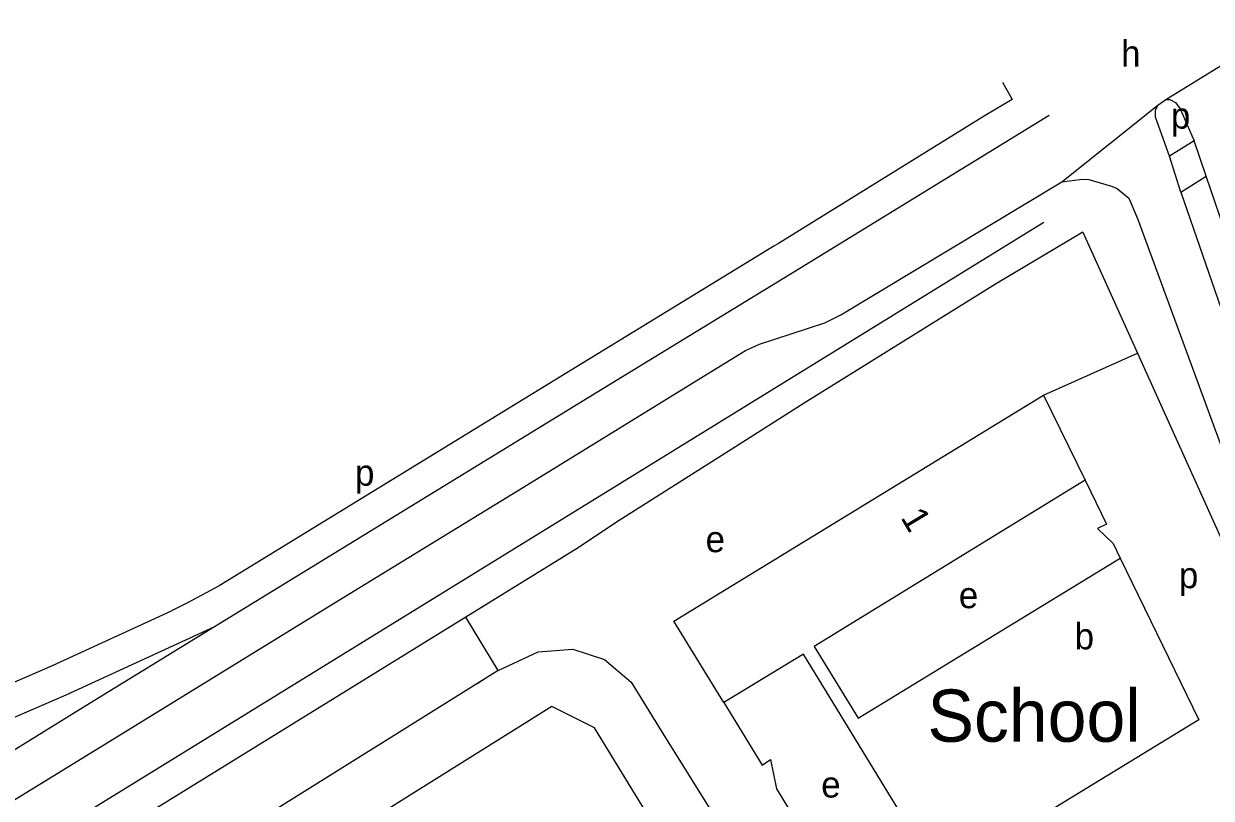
# Model space of a CAD drawing. Extents: x 158848 to 160613, y 385889 to 387762.
# Drawn here: x 158951 to 159133.1, y 387265.7 to 387384.4 of the extents above; entities that cross this region are included whole.
import ezdxf

# ---------------------------------------------------------------- set-up
doc = ezdxf.new("R2010")
doc.units = 0
for name, color, linetype in [('BLT_Basislijn', 7, 'Continuous'), ('BLT_Bebouwing', 7, 'Continuous'), ('BLT_Bebouwing_beschrifting', 7, 'Continuous'), ('BLT_Centroide', 7, 'Continuous'), ('BLT_Huisnummer', 7, 'Continuous'), ('BLT_Vlakafsluiter', 7, 'Continuous')]:
    doc.layers.add(name, color=color, linetype=linetype)

msp = doc.modelspace()

# ---------------------------------------------------------------- linework, layer by layer
at = {"layer": 'BLT_Basislijn'}
for p, q in [((159101.06, 387375.39), (159102.57, 387372.74)), ((159124.9, 387371.86), (159126.12, 387372.74)), ((159108.24, 387370.28), (159069.34, 387346.44)), ((159130.47, 387366.4), (159126.7, 387364.08)), ((159132.32, 387361.01), (159130.47, 387366.4)), ((159128.43, 387358.56), (159126.7, 387364.08)), ((159128.43, 387358.56), (159132.32, 387361.01)), ((159065.99, 387350.25), (159036.54, 387332.25)), ((159069.34, 387346.44), (159039.15, 387327.99)), ((159107.38, 387327.45), (159121.8, 387333.85)), ((159039.15, 387327.99), (158980.27, 387291.91)), ((159070.65, 387326.21), (159059.57, 387319.18)), ((159036.03, 387304.04), (159018.8, 387293.41)), ((158976.2, 387295.64), (158973.67, 387294.39)), ((159018.8, 387293.41), (158948.38, 387250)), ((159023.73, 387285.24), (159018.8, 387293.41)), ((158980.27, 387291.91), (158961.17, 387280.21)), ((159023.73, 387285.24), (158967.29, 387250)), ((158961.17, 387280.21), (158899.9, 387242.56)), ((159048.76, 387276.01), (159064.96, 387250))]:
    msp.add_line(p, q, dxfattribs=at)
for points in [[(159102.57, 387372.74), (159098.41, 387370.27), (159066.73, 387350.7), (159065.99, 387350.25)], [(159126.12, 387372.74), (159126.75, 387372.74), (159127.6, 387372.26), (159128.31, 387371.3), (159130.47, 387366.4)], [(159126.7, 387364.08), (159124.55, 387370.05), (159124.55, 387371.12), (159124.9, 387371.86)], [(158888.87, 387228.17), (158897.56, 387233.51), (158936.43, 387257.38), (158966.21, 387275.66), (158998.48, 387295.52), (159028.3, 387313.75), (159057.18, 387331.51), (159061.69, 387334.26), (159063.8, 387335.23), (159073.81, 387338.52), (159076.27, 387339.74), (159110.17, 387360.14)], [(159110.17, 387360.14), (159113.36, 387360.52), (159114.33, 387360.5), (159117.81, 387359.48), (159118.66, 387359.09), (159120.45, 387357.64), (159121.8, 387354.51)], [(159128.43, 387358.56), (159135.58, 387337.85), (159148.17, 387304.4), (159154.58, 387289.64), (159157.42, 387290.35), (159158.28, 387290.99), (159158.28, 387291.47), (159151.86, 387306.88), (159139.89, 387338.89), (159132.32, 387361.01)], [(159121.8, 387354.51), (159136.23, 387315.16), (159143.84, 387296.72), (159149.58, 387283.82)], [(158866.04, 387201.65), (158878.3, 387211.25), (158882.68, 387215.41), (158895.2, 387223.16), (158941.52, 387251.8), (159042.66, 387314.04), (159107.41, 387353.95)], [(159113.41, 387352.43), (159100, 387344.45), (159070.65, 387326.21)], [(159113.41, 387352.43), (159121.8, 387333.85)], [(159121.8, 387333.85), (159149.98, 387271.42)], [(159036.54, 387332.25), (158980.95, 387298.19), (158976.2, 387295.64)], [(159059.57, 387319.18), (159041.76, 387307.88), (159036.03, 387304.04)], [(159113.74, 387314.39), (159117, 387307.66), (159115.62, 387307.02), (159118.04, 387304.68), (159119.13, 387302.43)], [(158942.51, 387280.45), (158955.4, 387286.01), (158973.67, 387294.39)], [(158980.27, 387291.91), (158957.43, 387281.44), (158942.27, 387274.9)], [(159023.73, 387285.24), (159029.89, 387288.12), (159035.18, 387288.53), (159040.06, 387286.91), (159044.12, 387283.45), (159048.76, 387276.01)], [(159020.54, 387283.24), (159021.81, 387284.06)], [(159054.71, 387250), (159038.49, 387276.46), (159031.98, 387279.71), (159006.85, 387264)], [(159058.34, 387280.34), (159064.2, 387270.74), (159065.49, 387271.6), (159066.43, 387267.08), (159079.32, 387246.04)]]:
    msp.add_lwpolyline(points, dxfattribs=at)
at = {"layer": 'BLT_Bebouwing'}
for points in [[(159058.34, 387280.34), (159050.69, 387292.81), (159107.38, 387327.45)], [(159107.38, 387327.45), (159113.74, 387314.39)], [(159113.74, 387314.39), (159072.21, 387288.94), (159078.96, 387277.91), (159119.13, 387302.43)], [(159119.13, 387302.43), (159131.16, 387277.7), (159091.54, 387253.45)], [(159091.54, 387253.45), (159070.58, 387287.74), (159058.34, 387280.34)]]:
    msp.add_lwpolyline(points, dxfattribs=at)
at = {"layer": 'BLT_Vlakafsluiter'}
for p, q in [((159126.12, 387372.74), (159144.91, 387384.35)), ((159110.17, 387360.14), (159124.9, 387371.86))]:
    msp.add_line(p, q, dxfattribs=at)

# ---------------------------------------------------------------- texts
at = {"layer": 'BLT_Bebouwing_beschrifting'}
msp.add_text('School', height=8, dxfattribs=at).set_placement((159089.57, 387274.32))
at = {"layer": 'BLT_Centroide'}
for s, p in [('h', (159119.26, 387377.8)), ('p', (159126.9, 387368.28)), ('p', (159001.79, 387313.56)), ('e', (159055.55, 387303.37)), ('p', (159128.12, 387297.85)), ('e', (159094.38, 387294.79)), ('b', (159112.14, 387288.49)), ('e', (159073.28, 387265.77))]:
    msp.add_text(s, height=4, dxfattribs=at).set_placement(p)
at = {"layer": 'BLT_Huisnummer'}
msp.add_text('1', height=4, rotation=301.101, dxfattribs=at).set_placement((159085.37, 387308.68))

doc.saveas('drawing.dxf')
